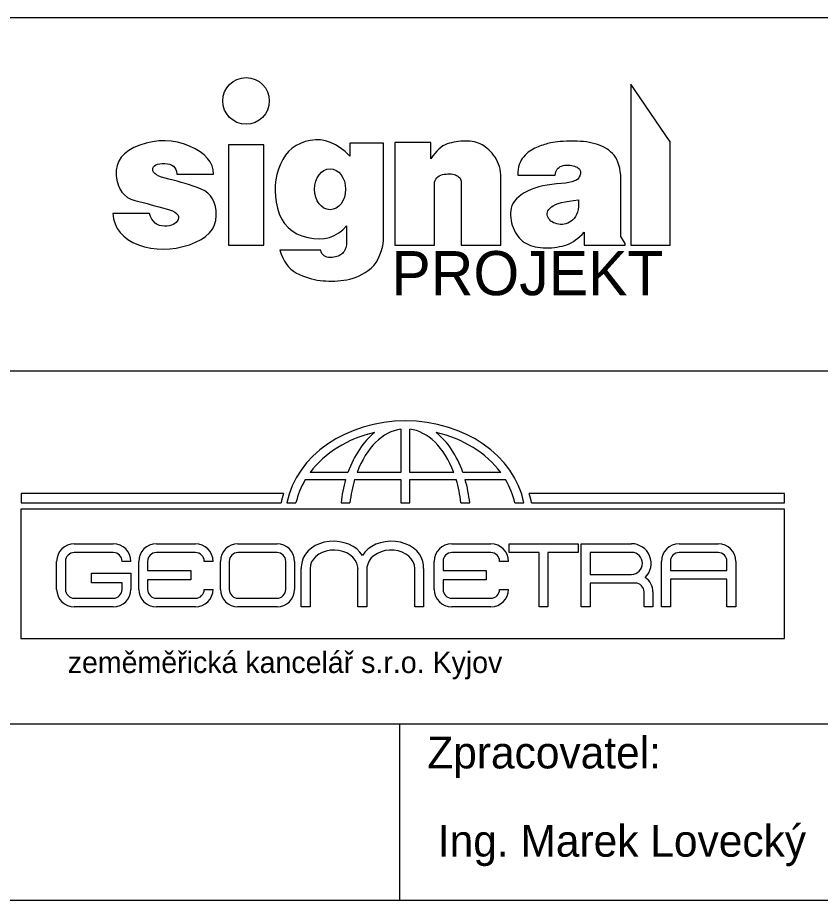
# Model space of a CAD drawing. Extents: x -558358 to -557517, y -1073785 to -1073189.
# Drawn here: x -557597.9 to -557552.4, y -1073682.1 to -1073632.1 of the extents above; entities that cross this region are included whole.
import ezdxf

# ---------------------------------------------------------------- set-up
doc = ezdxf.new("R2010")
doc.units = 0
for name, color, linetype in [('ROZPISKA', 7, 'Continuous'), ('Rozpiska_pole_6', 7, 'Continuous'), ('ZZZ - Razítko', 7, 'Continuous')]:
    doc.layers.add(name, color=color, linetype=linetype)

msp = doc.modelspace()

# ---------------------------------------------------------------- linework, layer by layer
at = {"layer": 'ROZPISKA'}
for points in [[(-557560.869, -1073644.967), (-557560.869, -1073639.127), (-557563.109, -1073635.847), (-557563.109, -1073644.967), (-557560.869, -1073644.967)], [(-557589.598, -1073645.202), (-557589.236, -1073645.186), (-557588.869, -1073645.138), (-557588.498, -1073645.059), (-557588.122, -1073644.948), (-557587.768, -1073644.812), (-557587.46, -1073644.656), (-557587.199, -1073644.48), (-557586.985, -1073644.284), (-557586.817, -1073644.068), (-557586.697, -1073643.832), (-557586.623, -1073643.576), (-557586.597, -1073643.301), (-557586.607, -1073643.027), (-557586.646, -1073642.778), (-557586.712, -1073642.554), (-557586.806, -1073642.355), (-557586.927, -1073642.18), (-557587.076, -1073642.03), (-557587.253, -1073641.904), (-557587.458, -1073641.804), (-557587.677, -1073641.718), (-557587.899, -1073641.636), (-557588.123, -1073641.558), (-557588.35, -1073641.486), (-557588.579, -1073641.417), (-557588.81, -1073641.353), (-557589.043, -1073641.293), (-557589.279, -1073641.238), (-557589.501, -1073641.183), (-557589.692, -1073641.124), (-557589.852, -1073641.061), (-557589.983, -1073640.994), (-557590.083, -1073640.922), (-557590.152, -1073640.847), (-557590.191, -1073640.768), (-557590.2, -1073640.685), (-557590.183, -1073640.605), (-557590.147, -1073640.537), (-557590.091, -1073640.479), (-557590.015, -1073640.431), (-557589.919, -1073640.395), (-557589.803, -1073640.37), (-557589.668, -1073640.355), (-557589.512, -1073640.351), (-557589.357, -1073640.362), (-557589.222, -1073640.391), (-557589.107, -1073640.439), (-557589.012, -1073640.504), (-557588.937, -1073640.588), (-557588.883, -1073640.69), (-557588.848, -1073640.811), (-557588.834, -1073640.949), (-557586.755, -1073640.949), (-557586.774, -1073640.708), (-557586.836, -1073640.478), (-557586.941, -1073640.261), (-557587.089, -1073640.057), (-557587.28, -1073639.865), (-557587.514, -1073639.686), (-557587.79, -1073639.52), (-557588.11, -1073639.367), (-557588.452, -1073639.237), (-557588.797, -1073639.143), (-557589.145, -1073639.083), (-557589.495, -1073639.058), (-557589.848, -1073639.068), (-557590.203, -1073639.113), (-557590.562, -1073639.193), (-557590.922, -1073639.307), (-557591.26, -1073639.45), (-557591.55, -1073639.612), (-557591.79, -1073639.796), (-557591.983, -1073640), (-557592.126, -1073640.224), (-557592.221, -1073640.469), (-557592.267, -1073640.734), (-557592.265, -1073641.02), (-557592.225, -1073641.302), (-557592.159, -1073641.554), (-557592.067, -1073641.776), (-557591.948, -1073641.969), (-557591.804, -1073642.132), (-557591.633, -1073642.266), (-557591.436, -1073642.37), (-557591.212, -1073642.445), (-557590.977, -1073642.505), (-557590.746, -1073642.565), (-557590.519, -1073642.624), (-557590.295, -1073642.683), (-557590.074, -1073642.741), (-557589.858, -1073642.8), (-557589.645, -1073642.858), (-557589.435, -1073642.916), (-557589.243, -1073642.976), (-557589.081, -1073643.04), (-557588.951, -1073643.109), (-557588.851, -1073643.182), (-557588.783, -1073643.26), (-557588.745, -1073643.343), (-557588.738, -1073643.429), (-557588.762, -1073643.521), (-557588.808, -1073643.609), (-557588.869, -1073643.685), (-557588.945, -1073643.75), (-557589.035, -1073643.803), (-557589.139, -1073643.844), (-557589.257, -1073643.874), (-557589.39, -1073643.893), (-557589.537, -1073643.899), (-557589.686, -1073643.889), (-557589.822, -1073643.856), (-557589.945, -1073643.8), (-557590.056, -1073643.722), (-557590.155, -1073643.62), (-557590.242, -1073643.497), (-557590.316, -1073643.35), (-557590.377, -1073643.182), (-557592.458, -1073643.182), (-557592.414, -1073643.488), (-557592.33, -1073643.771), (-557592.207, -1073644.028), (-557592.045, -1073644.262), (-557591.842, -1073644.472), (-557591.601, -1073644.657), (-557591.319, -1073644.818), (-557590.998, -1073644.954), (-557590.655, -1073645.063), (-557590.307, -1073645.141), (-557589.955, -1073645.187), (-557589.598, -1073645.202)], [(-557583.909, -1073644.967), (-557583.909, -1073639.287), (-557585.909, -1073639.287), (-557585.909, -1073644.967), (-557583.909, -1073644.967)], [(-557580.05, -1073647.009), (-557579.881, -1073647.006), (-557579.711, -1073646.997), (-557579.539, -1073646.984), (-557579.366, -1073646.965), (-557579.192, -1073646.939), (-557579.018, -1073646.9), (-557578.844, -1073646.848), (-557578.67, -1073646.785), (-557578.497, -1073646.71), (-557578.324, -1073646.622), (-557578.152, -1073646.522), (-557577.98, -1073646.41), (-557577.815, -1073646.281), (-557577.667, -1073646.128), (-557577.534, -1073645.952), (-557577.418, -1073645.753), (-557577.317, -1073645.531), (-557577.232, -1073645.286), (-557577.163, -1073645.018), (-557577.109, -1073644.727), (-557577.109, -1073639.207), (-557579.029, -1073639.207), (-557579.029, -1073639.927), (-557579.295, -1073639.673), (-557579.566, -1073639.46), (-557579.84, -1073639.288), (-557580.119, -1073639.157), (-557580.402, -1073639.067), (-557580.69, -1073639.018), (-557580.981, -1073639.01), (-557581.277, -1073639.044), (-557581.564, -1073639.112), (-557581.83, -1073639.209), (-557582.073, -1073639.334), (-557582.295, -1073639.488), (-557582.495, -1073639.67), (-557582.673, -1073639.881), (-557582.83, -1073640.121), (-557582.965, -1073640.388), (-557583.075, -1073640.674), (-557583.16, -1073640.967), (-557583.219, -1073641.267), (-557583.252, -1073641.575), (-557583.259, -1073641.889), (-557583.24, -1073642.211), (-557583.196, -1073642.54), (-557583.125, -1073642.876), (-557583.025, -1073643.199), (-557582.892, -1073643.49), (-557582.727, -1073643.748), (-557582.529, -1073643.974), (-557582.298, -1073644.166), (-557582.035, -1073644.326), (-557581.738, -1073644.454), (-557581.41, -1073644.548), (-557581.073, -1073644.606), (-557580.755, -1073644.624), (-557580.454, -1073644.6), (-557580.171, -1073644.536), (-557579.906, -1073644.432), (-557579.659, -1073644.286), (-557579.429, -1073644.1), (-557579.217, -1073643.873), (-557579.217, -1073644.95), (-557579.236, -1073645.037), (-557579.259, -1073645.119), (-557579.286, -1073645.195), (-557579.319, -1073645.265), (-557579.355, -1073645.33), (-557579.396, -1073645.388), (-557579.442, -1073645.441), (-557579.491, -1073645.489), (-557579.547, -1073645.53), (-557579.61, -1073645.567), (-557579.68, -1073645.598), (-557579.757, -1073645.623), (-557579.841, -1073645.643), (-557579.932, -1073645.658), (-557580.03, -1073645.667), (-557580.135, -1073645.671), (-557580.239, -1073645.666), (-557580.332, -1073645.647), (-557580.415, -1073645.616), (-557580.488, -1073645.571), (-557580.551, -1073645.512), (-557580.604, -1073645.441), (-557580.646, -1073645.356), (-557580.678, -1073645.258), (-557582.986, -1073645.258), (-557582.916, -1073645.485), (-557582.833, -1073645.694), (-557582.736, -1073645.884), (-557582.625, -1073646.056), (-557582.501, -1073646.208), (-557582.362, -1073646.342), (-557582.21, -1073646.457), (-557582.044, -1073646.554), (-557581.872, -1073646.637), (-557581.701, -1073646.711), (-557581.532, -1073646.776), (-557581.364, -1073646.833), (-557581.198, -1073646.882), (-557581.033, -1073646.922), (-557580.87, -1073646.953), (-557580.708, -1073646.975), (-557580.546, -1073646.991), (-557580.382, -1073647.002), (-557580.217, -1073647.008), (-557580.05, -1073647.009)], [(-557570.469, -1073644.967), (-557570.469, -1073641.167), (-557570.472, -1073640.997), (-557570.486, -1073640.834), (-557570.511, -1073640.677), (-557570.547, -1073640.527), (-557570.593, -1073640.384), (-557570.65, -1073640.247), (-557570.718, -1073640.117), (-557570.796, -1073639.993), (-557570.881, -1073639.877), (-557570.968, -1073639.769), (-557571.057, -1073639.669), (-557571.148, -1073639.577), (-557571.241, -1073639.494), (-557571.336, -1073639.418), (-557571.433, -1073639.351), (-557571.532, -1073639.293), (-557571.635, -1073639.241), (-557571.741, -1073639.197), (-557571.852, -1073639.16), (-557571.967, -1073639.129), (-557572.086, -1073639.106), (-557572.21, -1073639.089), (-557572.338, -1073639.079), (-557572.47, -1073639.077), (-557572.604, -1073639.08), (-557572.736, -1073639.088), (-557572.868, -1073639.101), (-557572.998, -1073639.119), (-557573.127, -1073639.142), (-557573.255, -1073639.17), (-557573.381, -1073639.202), (-557573.507, -1073639.24), (-557573.63, -1073639.288), (-557573.752, -1073639.353), (-557573.871, -1073639.434), (-557573.987, -1073639.532), (-557574.101, -1073639.646), (-557574.213, -1073639.777), (-557574.322, -1073639.924), (-557574.429, -1073640.087), (-557574.429, -1073639.167), (-557576.469, -1073639.167), (-557576.469, -1073644.967), (-557574.229, -1073644.967), (-557574.229, -1073641.407), (-557574.195, -1073641.316), (-557574.15, -1073641.235), (-557574.096, -1073641.164), (-557574.032, -1073641.103), (-557573.958, -1073641.052), (-557573.874, -1073641.011), (-557573.78, -1073640.98), (-557573.676, -1073640.959), (-557573.57, -1073640.946), (-557573.469, -1073640.939), (-557573.374, -1073640.938), (-557573.283, -1073640.944), (-557573.198, -1073640.955), (-557573.119, -1073640.973), (-557573.044, -1073640.996), (-557572.975, -1073641.026), (-557572.913, -1073641.061), (-557572.859, -1073641.099), (-557572.813, -1073641.141), (-557572.776, -1073641.187), (-557572.747, -1073641.237), (-557572.726, -1073641.29), (-557572.713, -1073641.347), (-557572.709, -1073641.407), (-557572.709, -1073644.967), (-557570.469, -1073644.967)], [(-557567.906, -1073645.131), (-557567.745, -1073645.128), (-557567.587, -1073645.12), (-557567.434, -1073645.105), (-557567.285, -1073645.085), (-557567.14, -1073645.06), (-557567, -1073645.028), (-557566.864, -1073644.991), (-557566.732, -1073644.948), (-557566.604, -1073644.896), (-557566.477, -1073644.835), (-557566.351, -1073644.763), (-557566.228, -1073644.681), (-557566.106, -1073644.588), (-557565.985, -1073644.485), (-557565.866, -1073644.371), (-557565.749, -1073644.247), (-557565.749, -1073644.967), (-557563.429, -1073644.967), (-557563.429, -1073644.887), (-557563.669, -1073644.487), (-557563.669, -1073641.007), (-557563.696, -1073640.803), (-557563.731, -1073640.612), (-557563.777, -1073640.437), (-557563.832, -1073640.276), (-557563.896, -1073640.129), (-557563.97, -1073639.997), (-557564.054, -1073639.879), (-557564.147, -1073639.775), (-557564.248, -1073639.683), (-557564.355, -1073639.597), (-557564.469, -1073639.518), (-557564.589, -1073639.446), (-557564.715, -1073639.381), (-557564.847, -1073639.323), (-557564.986, -1073639.272), (-557565.131, -1073639.228), (-557565.283, -1073639.19), (-557565.442, -1073639.158), (-557565.608, -1073639.131), (-557565.782, -1073639.11), (-557565.962, -1073639.095), (-557566.15, -1073639.086), (-557566.346, -1073639.082), (-557566.548, -1073639.085), (-557566.747, -1073639.091), (-557566.931, -1073639.099), (-557567.1, -1073639.109), (-557567.254, -1073639.122), (-557567.394, -1073639.137), (-557567.519, -1073639.154), (-557567.63, -1073639.174), (-557567.725, -1073639.195), (-557567.814, -1073639.219), (-557567.903, -1073639.245), (-557567.993, -1073639.272), (-557568.084, -1073639.302), (-557568.175, -1073639.333), (-557568.268, -1073639.367), (-557568.36, -1073639.402), (-557568.454, -1073639.44), (-557568.547, -1073639.481), (-557568.639, -1073639.53), (-557568.73, -1073639.585), (-557568.821, -1073639.647), (-557568.91, -1073639.716), (-557568.998, -1073639.792), (-557569.085, -1073639.875), (-557569.171, -1073639.964), (-557569.251, -1073640.062), (-557569.321, -1073640.169), (-557569.379, -1073640.285), (-557569.427, -1073640.411), (-557569.464, -1073640.546), (-557569.49, -1073640.69), (-557569.505, -1073640.844), (-557569.509, -1073641.007), (-557567.389, -1073641.007), (-557567.374, -1073640.911), (-557567.35, -1073640.824), (-557567.317, -1073640.746), (-557567.275, -1073640.677), (-557567.225, -1073640.617), (-557567.167, -1073640.567), (-557567.099, -1073640.525), (-557567.023, -1073640.493), (-557566.943, -1073640.469), (-557566.862, -1073640.451), (-557566.78, -1073640.439), (-557566.698, -1073640.435), (-557566.616, -1073640.436), (-557566.532, -1073640.445), (-557566.449, -1073640.459), (-557566.364, -1073640.481), (-557566.284, -1073640.506), (-557566.213, -1073640.534), (-557566.15, -1073640.564), (-557566.097, -1073640.596), (-557566.051, -1073640.63), (-557566.015, -1073640.666), (-557565.987, -1073640.705), (-557565.969, -1073640.745), (-557565.957, -1073640.788), (-557565.952, -1073640.834), (-557565.953, -1073640.883), (-557565.961, -1073640.934), (-557565.974, -1073640.988), (-557565.994, -1073641.045), (-557566.021, -1073641.105), (-557566.053, -1073641.168), (-557566.104, -1073641.229), (-557566.185, -1073641.285), (-557566.296, -1073641.335), (-557566.438, -1073641.381), (-557566.61, -1073641.421), (-557566.812, -1073641.456), (-557567.045, -1073641.485), (-557567.308, -1073641.509), (-557567.58, -1073641.536), (-557567.839, -1073641.573), (-557568.086, -1073641.621), (-557568.321, -1073641.68), (-557568.544, -1073641.749), (-557568.755, -1073641.828), (-557568.953, -1073641.918), (-557569.139, -1073642.019), (-557569.308, -1073642.127), (-557569.456, -1073642.24), (-557569.584, -1073642.357), (-557569.69, -1073642.479), (-557569.776, -1073642.605), (-557569.841, -1073642.735), (-557569.885, -1073642.871), (-557569.908, -1073643.01), (-557569.916, -1073643.152), (-557569.915, -1073643.292), (-557569.905, -1073643.431), (-557569.886, -1073643.569), (-557569.858, -1073643.705), (-557569.821, -1073643.841), (-557569.775, -1073643.975), (-557569.72, -1073644.108), (-557569.657, -1073644.237), (-557569.587, -1073644.356), (-557569.51, -1073644.466), (-557569.426, -1073644.568), (-557569.335, -1073644.66), (-557569.238, -1073644.744), (-557569.133, -1073644.819), (-557569.022, -1073644.885), (-557568.904, -1073644.943), (-557568.78, -1073644.993), (-557568.65, -1073645.035), (-557568.513, -1073645.07), (-557568.371, -1073645.097), (-557568.222, -1073645.116), (-557568.067, -1073645.127), (-557567.906, -1073645.131)], [(-557567.191, -1073643.787), (-557567.294, -1073643.766), (-557567.388, -1073643.738), (-557567.475, -1073643.702), (-557567.554, -1073643.659), (-557567.625, -1073643.607), (-557567.688, -1073643.548), (-557567.743, -1073643.481), (-557567.789, -1073643.407), (-557567.824, -1073643.329), (-557567.842, -1073643.252), (-557567.843, -1073643.176), (-557567.827, -1073643.101), (-557567.795, -1073643.027), (-557567.746, -1073642.954), (-557567.68, -1073642.881), (-557567.597, -1073642.81), (-557567.494, -1073642.742), (-557567.365, -1073642.679), (-557567.211, -1073642.621), (-557567.032, -1073642.568), (-557566.828, -1073642.521), (-557566.599, -1073642.479), (-557566.344, -1073642.443), (-557566.064, -1073642.412), (-557566.06, -1073642.61), (-557566.069, -1073642.792), (-557566.091, -1073642.958), (-557566.125, -1073643.108), (-557566.173, -1073643.241), (-557566.233, -1073643.359), (-557566.306, -1073643.46), (-557566.393, -1073643.545), (-557566.486, -1073643.617), (-557566.582, -1073643.676), (-557566.679, -1073643.724), (-557566.778, -1073643.76), (-557566.878, -1073643.784), (-557566.981, -1073643.797), (-557567.085, -1073643.798), (-557567.191, -1073643.787)]]:
    msp.add_lwpolyline(points, dxfattribs=at)
msp.add_circle((-557584.909, -1073636.807), 1.32, dxfattribs=at)
msp.add_ellipse((-557580.149, -1073641.807), major_axis=(0, 1.16), ratio=0.758621, dxfattribs=at)
at = {"layer": 'Rozpiska_pole_6'}
for p, q in [((-557706.534, -1073652.088), (-557536.534, -1073652.088)), ((-557706.534, -1073672.088), (-557536.534, -1073672.088)), ((-557576.184, -1073682.088), (-557576.184, -1073672.088))]:
    msp.add_line(p, q, dxfattribs=at)
msp.add_lwpolyline([(-557706.534, -1073632.088), (-557536.534, -1073632.088), (-557536.534, -1073682.088), (-557706.534, -1073682.088)], close=True, dxfattribs=at)
at = {"layer": 'ZZZ - Razítko'}
for p, q in [((-557576.139, -1073655.401), (-557576.139, -1073657.847)), ((-557575.632, -1073657.847), (-557575.632, -1073655.399)), ((-557579.132, -1073657.847), (-557581.277, -1073657.847)), ((-557576.139, -1073657.847), (-557578.615, -1073657.847)), ((-557573.137, -1073657.847), (-557575.632, -1073657.847)), ((-557570.475, -1073657.847), (-557572.62, -1073657.847)), ((-557581.552, -1073658.258), (-557579.265, -1073658.258)), ((-557578.755, -1073658.258), (-557576.139, -1073658.258)), ((-557576.139, -1073658.258), (-557576.139, -1073659.578)), ((-557575.632, -1073659.578), (-557575.632, -1073658.258)), ((-557575.632, -1073658.258), (-557572.998, -1073658.258)), ((-557572.488, -1073658.258), (-557570.2, -1073658.258)), ((-557582.783, -1073659.047), (-557597.663, -1073659.047)), ((-557597.663, -1073659.047), (-557597.663, -1073659.578)), ((-557554.385, -1073659.047), (-557568.863, -1073659.047)), ((-557554.385, -1073659.578), (-557554.385, -1073659.047)), ((-557554.387, -1073659.923), (-557597.67, -1073659.923)), ((-557597.67, -1073659.923), (-557597.67, -1073667.261)), ((-557597.663, -1073659.578), (-557582.921, -1073659.578)), ((-557582.595, -1073659.578), (-557582.078, -1073659.578)), ((-557579.522, -1073659.578), (-557579.022, -1073659.578)), ((-557576.139, -1073659.578), (-557575.632, -1073659.578)), ((-557572.731, -1073659.578), (-557572.23, -1073659.578)), ((-557569.674, -1073659.578), (-557569.157, -1073659.578)), ((-557568.725, -1073659.578), (-557554.385, -1073659.578)), ((-557554.387, -1073667.261), (-557554.387, -1073659.923)), ((-557594.645, -1073661.889), (-557592.434, -1073661.889)), ((-557589.989, -1073661.889), (-557587.778, -1073661.889)), ((-557585.365, -1073661.889), (-557583.154, -1073661.889)), ((-557573.246, -1073661.889), (-557571.036, -1073661.889)), ((-557565.909, -1073661.889), (-557563.064, -1073661.889)), ((-557560.361, -1073661.889), (-557558.15, -1073661.889)), ((-557592.434, -1073662.387), (-557594.645, -1073662.387)), ((-557587.778, -1073662.387), (-557589.989, -1073662.387)), ((-557583.154, -1073662.387), (-557585.365, -1073662.387)), ((-557571.036, -1073662.387), (-557573.246, -1073662.387)), ((-557568.303, -1073665.471), (-557568.303, -1073662.375)), ((-557567.8, -1073662.375), (-557567.8, -1073665.471)), ((-557563.064, -1073662.378), (-557565.405, -1073662.378)), ((-557565.405, -1073662.378), (-557565.405, -1073663.627)), ((-557558.15, -1073662.387), (-557560.361, -1073662.387)), ((-557595.643, -1073664.473), (-557595.643, -1073662.887)), ((-557595.144, -1073662.887), (-557595.144, -1073664.473)), ((-557591.437, -1073662.887), (-557591.935, -1073662.887)), ((-557590.986, -1073664.473), (-557590.986, -1073662.887)), ((-557590.488, -1073662.887), (-557590.488, -1073663.397)), ((-557586.78, -1073662.887), (-557587.279, -1073662.887)), ((-557586.363, -1073664.473), (-557586.363, -1073662.887)), ((-557585.864, -1073662.887), (-557585.864, -1073664.473)), ((-557582.655, -1073664.473), (-557582.655, -1073662.887)), ((-557582.156, -1073662.887), (-557582.156, -1073664.473)), ((-557574.244, -1073664.473), (-557574.244, -1073662.887)), ((-557573.745, -1073662.887), (-557573.745, -1073663.397)), ((-557570.038, -1073662.887), (-557570.536, -1073662.887)), ((-557561.359, -1073665.471), (-557561.359, -1073662.887)), ((-557560.86, -1073662.887), (-557560.86, -1073663.395)), ((-557557.651, -1073663.395), (-557557.651, -1073662.887)), ((-557557.152, -1073662.887), (-557557.152, -1073665.471)), ((-557590.488, -1073663.397), (-557588.045, -1073663.397)), ((-557588.045, -1073663.397), (-557588.045, -1073663.942)), ((-557581.784, -1073665.471), (-557581.784, -1073663.286)), ((-557581.283, -1073663.286), (-557581.283, -1073665.471)), ((-557578.564, -1073665.471), (-557578.564, -1073663.286)), ((-557578.063, -1073663.286), (-557578.063, -1073665.471)), ((-557575.345, -1073665.471), (-557575.345, -1073663.286)), ((-557574.844, -1073663.286), (-557574.844, -1073665.471)), ((-557573.745, -1073663.397), (-557571.302, -1073663.397)), ((-557571.302, -1073663.397), (-557571.302, -1073663.942)), ((-557560.86, -1073663.395), (-557557.651, -1073663.395)), ((-557593.67, -1073664.095), (-557593.67, -1073663.55)), ((-557593.67, -1073663.55), (-557591.437, -1073663.55)), ((-557591.437, -1073663.55), (-557591.437, -1073664.473)), ((-557588.045, -1073663.942), (-557590.488, -1073663.942)), ((-557590.488, -1073663.942), (-557590.488, -1073664.473)), ((-557571.302, -1073663.942), (-557573.745, -1073663.942)), ((-557573.745, -1073663.942), (-557573.745, -1073664.473)), ((-557565.405, -1073663.627), (-557563.064, -1073663.627)), ((-557557.651, -1073663.899), (-557560.86, -1073663.899)), ((-557560.86, -1073663.899), (-557560.86, -1073665.471)), ((-557557.651, -1073665.471), (-557557.651, -1073663.899)), ((-557591.935, -1073664.095), (-557593.67, -1073664.095)), ((-557591.935, -1073664.473), (-557591.935, -1073664.095)), ((-557587.279, -1073664.473), (-557586.78, -1073664.473)), ((-557570.536, -1073664.473), (-557570.038, -1073664.473)), ((-557563.064, -1073664.116), (-557565.405, -1073664.116)), ((-557562.85, -1073664.12), (-557563.064, -1073664.116)), ((-557594.645, -1073664.972), (-557592.434, -1073664.972)), ((-557589.989, -1073664.972), (-557587.778, -1073664.972)), ((-557585.365, -1073664.972), (-557583.154, -1073664.972)), ((-557573.246, -1073664.972), (-557571.036, -1073664.972)), ((-557562.351, -1073665.471), (-557562.351, -1073664.619)), ((-557561.853, -1073664.619), (-557561.853, -1073665.471)), ((-557592.434, -1073665.471), (-557594.645, -1073665.471)), ((-557587.778, -1073665.471), (-557589.989, -1073665.471)), ((-557583.154, -1073665.471), (-557585.365, -1073665.471)), ((-557581.283, -1073665.471), (-557581.784, -1073665.471)), ((-557578.063, -1073665.471), (-557578.564, -1073665.471)), ((-557574.844, -1073665.471), (-557575.345, -1073665.471)), ((-557571.036, -1073665.471), (-557573.246, -1073665.471)), ((-557567.8, -1073665.471), (-557568.303, -1073665.471)), ((-557561.853, -1073665.471), (-557562.351, -1073665.471)), ((-557560.86, -1073665.471), (-557561.359, -1073665.471)), ((-557557.152, -1073665.471), (-557557.651, -1073665.471)), ((-557597.67, -1073667.261), (-557554.387, -1073667.261))]:
    msp.add_line(p, q, dxfattribs=at)
for points in [[(-557568.303, -1073662.375), (-557570.001, -1073662.375), (-557570.001, -1073661.889), (-557566.087, -1073661.889)], [(-557566.087, -1073661.889), (-557566.087, -1073662.375), (-557567.8, -1073662.375)], [(-557565.405, -1073664.116), (-557565.405, -1073665.471), (-557565.909, -1073665.471), (-557565.909, -1073661.889)]]:
    msp.add_lwpolyline(points, dxfattribs=at)
for centre, radius, start, end in [((-557594.645, -1073662.887), 0.998, 90, 180), ((-557592.434, -1073662.887), 0.998, 360, 90), ((-557589.989, -1073662.887), 0.998, 90, 180), ((-557587.778, -1073662.887), 0.998, 360, 90), ((-557585.365, -1073662.887), 0.998, 90, 180), ((-557583.154, -1073662.887), 0.998, 360, 90), ((-557573.246, -1073662.887), 0.998, 90, 180), ((-557571.036, -1073662.887), 0.998, 360, 90), ((-557563.064, -1073663.003), 1.114, 314.4573, 90), ((-557560.361, -1073662.887), 0.998, 90, 180), ((-557558.15, -1073662.887), 0.998, 360, 90), ((-557594.645, -1073662.887), 0.499, 90, 180), ((-557592.434, -1073662.887), 0.499, 0, 90), ((-557589.989, -1073662.887), 0.499, 90, 180), ((-557587.778, -1073662.887), 0.499, 0, 90), ((-557585.365, -1073662.887), 0.499, 90, 180), ((-557583.154, -1073662.887), 0.499, 0, 90), ((-557573.246, -1073662.887), 0.499, 90, 180), ((-557571.036, -1073662.887), 0.499, 0, 90), ((-557563.064, -1073663.003), 0.625, 270, 90), ((-557560.361, -1073662.887), 0.499, 90, 180), ((-557558.15, -1073662.887), 0.499, 0, 90), ((-557579.846, -1073663.336), 1.938, 166.9658, 178.5209), ((-557579.518, -1073663.35), 0.957, 3.8649, 22.4157), ((-557576.782, -1073663.336), 1.938, 1.4791, 13.0342), ((-557576.831, -1073663.408), 1.238, 162.6139, 174.3506), ((-557562.85, -1073664.619), 0.998, 360, 55.4473), ((-557594.645, -1073664.473), 0.998, 180, 270), ((-557594.645, -1073664.473), 0.499, 180, 270), ((-557592.434, -1073664.473), 0.998, 270, 0), ((-557592.434, -1073664.473), 0.499, 270, 0), ((-557589.989, -1073664.473), 0.998, 180, 270), ((-557589.989, -1073664.473), 0.499, 180, 270), ((-557587.778, -1073664.473), 0.998, 270, 0), ((-557587.778, -1073664.473), 0.499, 270, 0), ((-557585.365, -1073664.473), 0.998, 180, 270), ((-557585.365, -1073664.473), 0.499, 180, 270), ((-557583.154, -1073664.473), 0.998, 270, 0), ((-557583.154, -1073664.473), 0.499, 270, 0), ((-557573.246, -1073664.473), 0.998, 180, 270), ((-557573.246, -1073664.473), 0.499, 180, 270), ((-557571.036, -1073664.473), 0.998, 270, 0), ((-557571.036, -1073664.473), 0.499, 270, 0), ((-557562.85, -1073664.619), 0.499, 0, 90)]:
    msp.add_arc(centre, radius, start, end, dxfattribs=at)
for centre, major_axis, ratio, start_param, end_param in [((-557575.876, -1073660.451), (-6.804, 0), 0.811768, 3.300239, 6.124539), ((-557575.876, -1073660.451), (0, 5.067), 0.630136, 0.08224, 1.030995), ((-557575.876, -1073660.451), (0, 5.067), 0.630136, 5.252191, 6.206521), ((-557575.876, -1073660.451), (-6.296, 0), 0.804826, 4.992897, 5.743383), ((-557575.876, -1073660.451), (0, 5.524), 0.668443, 0.491666, 1.079789), ((-557575.876, -1073660.451), (0, 5.524), 0.668443, 5.203397, 5.79152), ((-557575.876, -1073660.451), (-6.296, 0), 0.804826, 3.681394, 4.431881), ((-557575.876, -1073660.451), (-6.296, 0), 0.804826, 5.835664, 6.110118), ((-557575.876, -1073660.451), (0, 5.524), 0.668443, 1.16256, 1.41215), ((-557575.876, -1073660.451), (0, 5.067), 0.630136, 1.123275, 1.397729), ((-557575.876, -1073660.451), (0, 5.067), 0.630136, 4.885456, 5.159911), ((-557575.876, -1073660.451), (0, 5.524), 0.668443, 4.871035, 5.120625), ((-557575.876, -1073660.451), (-6.296, 0), 0.804826, 3.31466, 3.589114), ((-557576.202, -1073660.451), (-6.804, 0), 0.811768, 6.026233, 6.124539), ((-557575.444, -1073660.451), (-6.804, 0), 0.811768, 3.300239, 3.398545), ((-557579.955, -1073663.13), (1.805, 0), 0.766187, 0.429647, 2.97338), ((-557576.673, -1073663.13), (-1.805, 0), 0.766187, 3.309805, 5.853538), ((-557579.93, -1073663.286), (1.354, 0), 0.766187, 0.29376, 3.141593), ((-557576.698, -1073663.286), (-1.354, 0), 0.766187, 3.141593, 6.041607)]:
    msp.add_ellipse(centre, major_axis=major_axis, ratio=ratio, start_param=start_param, end_param=end_param, dxfattribs=at)

# ---------------------------------------------------------------- texts
at = {"layer": 'ROZPISKA'}
msp.add_text('PROJEKT', height=2.5, dxfattribs=at).set_placement((-557576.669, -1073647.81))
at = {"layer": 'Rozpiska_pole_6'}
for s, p in [('Zpracovatel:', (-557574.638, -1073674.615)), ('Ing. Marek Lovecký', (-557574.037, -1073679.615))]:
    msp.add_text(s, height=1.8, dxfattribs=at).set_placement(p)
at = {"layer": 'ZZZ - Razítko'}
msp.add_text('zeměměřická kancelář s.r.o. Kyjov', height=1.20984, dxfattribs=at).set_placement((-557595.018, -1073669.21))

doc.saveas('drawing.dxf')
